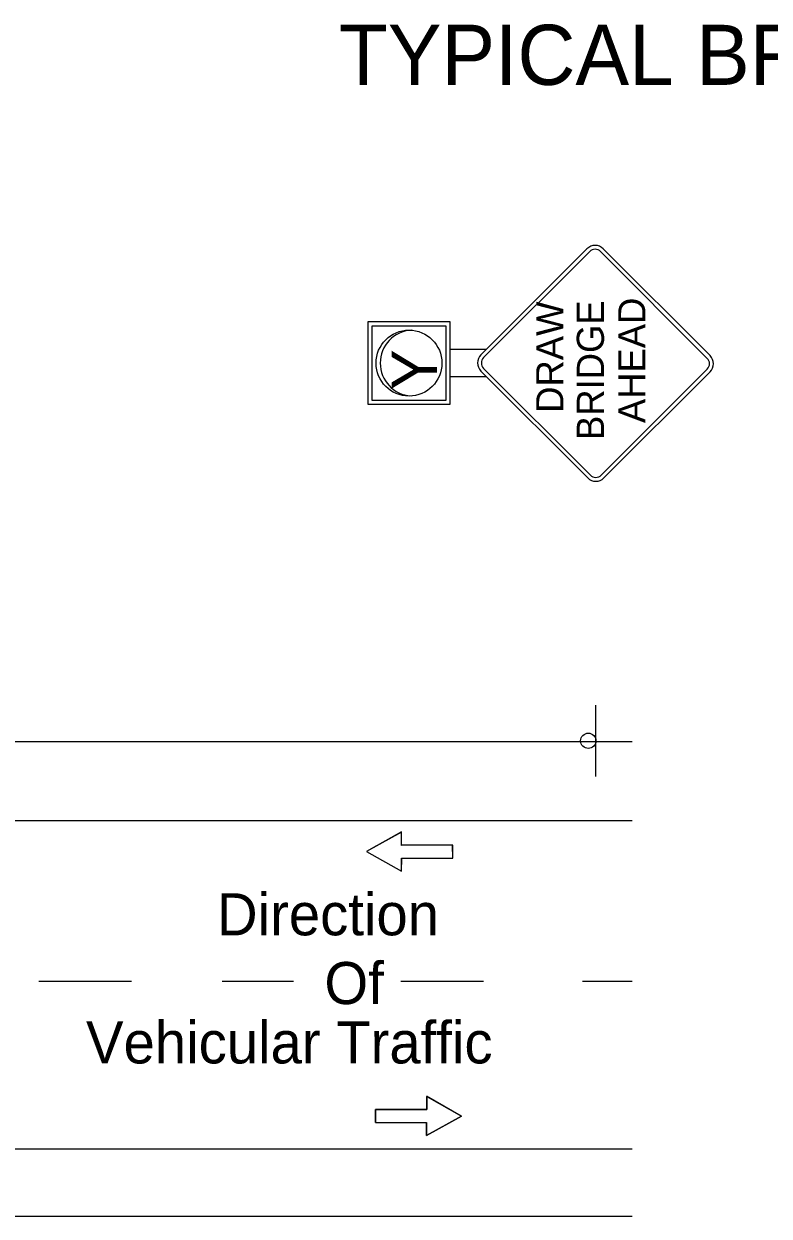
# Model space of a CAD drawing. Extents: x 10000 to 10825, y 10000 to 10530.
# Drawn here: x 10343.8 to 10405.7, y 10404.8 to 10503.9 of the extents above; entities that cross this region are included whole.
import ezdxf

# ---------------------------------------------------------------- set-up
doc = ezdxf.new("R2010")
doc.units = 0
doc.layers.add('Default', color=7, linetype='Continuous')
doc.layers.add('TextStructures', color=7, linetype='Continuous')

msp = doc.modelspace()

# ---------------------------------------------------------------- linework, layer by layer
at = {"layer": 'Default'}
for p, q in [((10390.594, 10485.229), (10381.773, 10476.414)), ((10390.822, 10485.001), (10382.002, 10476.185)), ((10400.602, 10476.115), (10391.72, 10485.001)), ((10400.83, 10476.344), (10391.948, 10485.229)), ((10379.219, 10479.151), (10372.368, 10479.151)), ((10372.368, 10479.151), (10372.368, 10472.3)), ((10378.876, 10478.808), (10372.711, 10478.808)), ((10372.711, 10478.808), (10372.711, 10472.643)), ((10378.876, 10472.643), (10378.876, 10478.808)), ((10379.219, 10472.3), (10379.219, 10479.151)), ((10382.201, 10476.843), (10379.228, 10476.843)), ((10382.252, 10474.578), (10379.228, 10474.578)), ((10390.655, 10466.172), (10381.772, 10475.059)), ((10390.883, 10466.401), (10382.001, 10475.287)), ((10400.602, 10475.216), (10391.781, 10466.401)), ((10400.83, 10474.988), (10392.009, 10466.172)), ((10372.711, 10472.643), (10378.876, 10472.643)), ((10372.368, 10472.3), (10379.219, 10472.3)), ((10391.344, 10441.343), (10391.344, 10447.287)), ((10049.563, 10444.263), (10394.364, 10444.263)), ((10049.563, 10437.701), (10394.364, 10437.701)), ((10375.17, 10436.728), (10372.256, 10435.106)), ((10375.166, 10436.726), (10372.848, 10435.436)), ((10375.166, 10435.639), (10375.17, 10436.728)), ((10372.256, 10435.106), (10375.158, 10433.463)), ((10379.425, 10435.641), (10375.166, 10435.639)), ((10379.431, 10434.55), (10379.425, 10435.641)), ((10375.158, 10433.463), (10375.162, 10434.552)), ((10375.158, 10433.463), (10375.162, 10434.552)), ((10375.162, 10434.552), (10379.431, 10434.55)), ((10375.162, 10434.552), (10375.183, 10434.552)), ((10344.997, 10424.324), (10352.716, 10424.324)), ((10360.255, 10424.324), (10366.186, 10424.324)), ((10375.105, 10424.324), (10381.987, 10424.324)), ((10390.227, 10424.324), (10394.364, 10424.324)), ((10377.266, 10414.755), (10377.262, 10413.665)), ((10380.168, 10413.112), (10377.266, 10414.755)), ((10377.262, 10413.665), (10373.003, 10413.658)), ((10373.003, 10413.658), (10373.01, 10412.57)), ((10377.254, 10411.489), (10380.168, 10413.112)), ((10377.254, 10411.489), (10380.168, 10413.112)), ((10373.01, 10412.57), (10377.258, 10412.57)), ((10373.01, 10412.57), (10377.258, 10412.57)), ((10377.258, 10412.57), (10377.254, 10411.489)), ((10377.258, 10412.57), (10377.254, 10411.489)), ((10049.563, 10410.382), (10394.364, 10410.382)), ((10049.563, 10404.79), (10394.364, 10404.79)), ((10299.958, 10404.79), (10394.364, 10404.79))]:
    msp.add_line(p, q, dxfattribs=at)
for points in [[(10379.421, 10435.65), (10375.166, 10435.616), (10375.166, 10436.745), (10372.261, 10435.104), (10375.158, 10433.463), (10375.183, 10434.552), (10379.431, 10434.555)], [(10373.003, 10413.651), (10377.267, 10413.672), (10377.267, 10414.749), (10380.168, 10413.112), (10377.254, 10411.499), (10377.258, 10412.553), (10373.01, 10412.57)]]:
    msp.add_lwpolyline(points, close=True, dxfattribs=at)
for points in [[(10375.183, 10434.552), (10379.431, 10434.555), (10379.421, 10435.65), (10375.166, 10435.616), (10375.166, 10436.726)], [(10372.848, 10435.436), (10372.261, 10435.104), (10375.158, 10433.463)], [(10380.168, 10413.112), (10377.267, 10414.749), (10377.267, 10413.672), (10373.003, 10413.651), (10373.01, 10412.57)]]:
    msp.add_lwpolyline(points, dxfattribs=at)
for centre, radius in [((10375.794, 10475.726), 2.74), ((10390.707, 10444.315), 0.637)]:
    msp.add_circle(centre, radius, dxfattribs=at)
for centre, radius, start, end in [((10391.271, 10484.553), 0.958, 44.98483, 134.9852), ((10391.271, 10484.553), 0.635, 44.98483, 134.9852), ((10376.136, 10475.726), 2.74, 93.58332, 266.41668), ((10382.45, 10475.737), 0.958, 134.98524, 224.9843), ((10382.45, 10475.737), 0.635, 134.98524, 224.9843), ((10400.152, 10475.667), 0.635, 314.98573, 44.98455), ((10400.152, 10475.667), 0.958, 314.98573, 44.98455), ((10391.331, 10466.851), 0.958, 224.98473, 314.98571), ((10391.331, 10466.851), 0.635, 224.98473, 314.98571)]:
    msp.add_arc(centre, radius, start, end, dxfattribs=at)

# ---------------------------------------------------------------- texts
for s, height, p in [('DRAW', 2.2646, (10388.636, 10471.589)), ('BRIDGE', 2.2646, (10392.009, 10469.329)), ('AHEAD', 2.2646, (10395.457, 10470.735)), ('Y', 3.78, (10378.132, 10473.492))]:
    msp.add_text(s, height=height, rotation=90, dxfattribs=at).set_placement(p)
at = {"layer": 'TextStructures'}
msp.add_text('TYPICAL BRIDGE MOUNTS', height=5, rotation=0.00072, dxfattribs=at).set_placement((10369.949, 10498.858))
for s, p in [('Direction', (10359.821, 10428.141)), ('Of', (10368.757, 10422.423)), ('Vehicular Traffic', (10348.929, 10417.488))]:
    msp.add_text(s, height=3.5, dxfattribs=at).set_placement(p)

doc.saveas('drawing.dxf')
